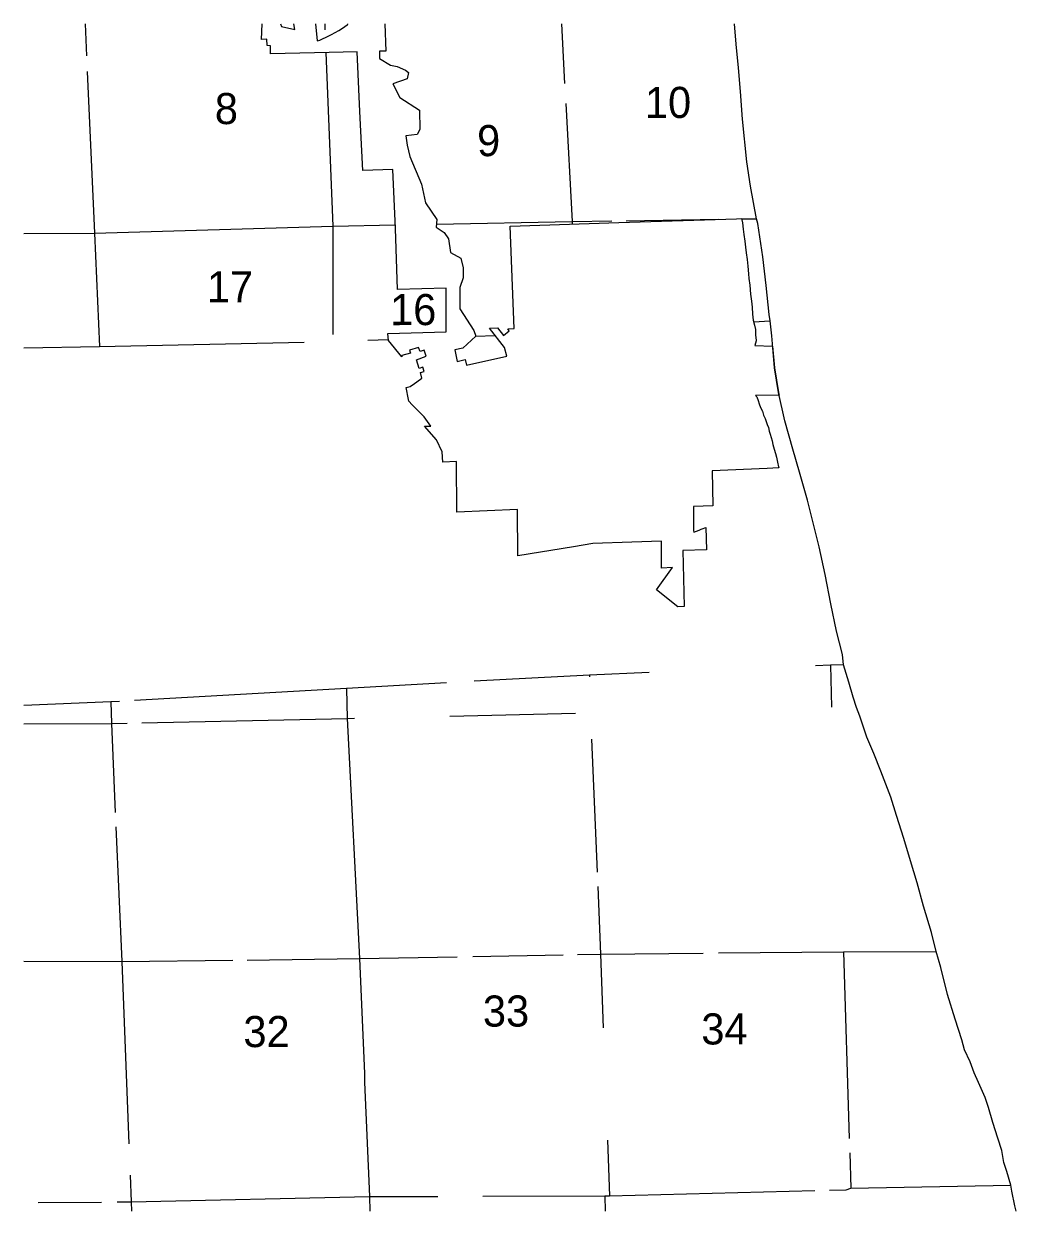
# Model space of a CAD drawing. Extents: x -2251611 to -2054719, y -2227156 to -2099355.
# Drawn here: x -2096698 to -2074784, y -2144490 to -2118284 of the extents above; entities that cross this region are included whole.
import ezdxf

# ---------------------------------------------------------------- set-up
doc = ezdxf.new("R2010")
doc.units = 0
for name, color, linetype in [('tdCoCorpBndry', 7, 'Continuous'), ('tdCoSectLinePart', 7, 'Continuous'), ('tdCoSectNmbr', 7, 'Continuous')]:
    doc.layers.add(name, color=color, linetype=linetype)

msp = doc.modelspace()

# ---------------------------------------------------------------- linework, layer by layer
at = {"layer": 'tdCoCorpBndry'}
for points in [[(-2088724, -2118284), (-2088705, -2118887), (-2088844, -2118891), (-2088842, -2119050), (-2088604, -2119197), (-2088450, -2119224), (-2088268, -2119308), (-2088200, -2119360), (-2088232, -2119497), (-2088546, -2119610), (-2088395, -2119912), (-2087962, -2120191), (-2087954, -2120618), (-2088013, -2120731), (-2088259, -2120757), (-2088230, -2120966), (-2088174, -2121214), (-2087918, -2121827), (-2087828, -2122237), (-2087578, -2122601), (-2087589, -2122774), (-2087416, -2122890), (-2087317, -2123029), (-2087273, -2123331), (-2087050, -2123455), (-2086994, -2123670), (-2086998, -2123894), (-2087071, -2124104), (-2087070, -2124578), (-2086761, -2125054), (-2086720, -2125175), (-2087002, -2125445), (-2087183, -2125483), (-2087130, -2125736), (-2086952, -2125696), (-2086923, -2125816), (-2086030, -2125619), (-2086080, -2125429), (-2086412, -2125000), (-2086240, -2124998), (-2086104, -2125164), (-2085979, -2125060), (-2086009, -2125016), (-2085873, -2125011), (-2085959, -2122752), (-2083559, -2122673), (-2080958, -2122587), (-2080853, -2122584), (-2080831, -2122679), (-2080815, -2122818), (-2080800, -2122938), (-2080778, -2123083), (-2080762, -2123218), (-2080745, -2123336), (-2080727, -2123489), (-2080714, -2123635), (-2080697, -2123802), (-2080685, -2123908), (-2080665, -2124051), (-2080650, -2124254), (-2080632, -2124406), (-2080618, -2124541), (-2080610, -2124693), (-2080592, -2124828), (-2080561, -2124939), (-2080545, -2125034), (-2080538, -2125154), (-2080528, -2125264), (-2080529, -2125285), (-2080556, -2125388), (-2080163, -2125396), (-2080120, -2125877), (-2080034, -2126421), (-2080021, -2126480), (-2080027, -2126480), (-2080539, -2126485), (-2080511, -2126516), (-2080485, -2126601), (-2080460, -2126672), (-2080431, -2126753), (-2080387, -2126837), (-2080362, -2126920), (-2080331, -2126999), (-2080308, -2127062), (-2080281, -2127129), (-2080258, -2127196), (-2080237, -2127273), (-2080218, -2127344), (-2080193, -2127417), (-2080174, -2127491), (-2080158, -2127572), (-2080130, -2127671), (-2080102, -2127768), (-2080081, -2127851), (-2080058, -2127962), (-2080032, -2128059), (-2080025, -2128085), (-2080156, -2128090), (-2080287, -2128096), (-2081495, -2128147), (-2081484, -2128923), (-2081911, -2128941), (-2081907, -2129477), (-2081906, -2129503), (-2081782, -2129457), (-2081739, -2129441), (-2081716, -2129433), (-2081638, -2129404), (-2081621, -2129891), (-2082143, -2129909), (-2082119, -2131143), (-2082257, -2131151), (-2082724, -2130776), (-2082374, -2130282), (-2082620, -2130298), (-2082619, -2130082), (-2082620, -2129704), (-2083271, -2129727), (-2084131, -2129757), (-2084557, -2129827), (-2085788, -2130029), (-2085794, -2129001), (-2087135, -2129063), (-2087141, -2127942), (-2087445, -2127957), (-2087459, -2127728), (-2087582, -2127463), (-2087852, -2127162), (-2087708, -2127162), (-2087858, -2126961), (-2088120, -2126691), (-2088196, -2126612), (-2088203, -2126578), (-2088257, -2126309), (-2088163, -2126286), (-2088112, -2126249), (-2088102, -2126243), (-2087910, -2126106), (-2087939, -2125982), (-2087859, -2125960), (-2087886, -2125862), (-2087966, -2125889), (-2088028, -2125698), (-2087813, -2125617), (-2087855, -2125488), (-2087949, -2125519), (-2087980, -2125428), (-2088180, -2125491), (-2088160, -2125551), (-2088353, -2125605), (-2088348, -2125636), (-2088642, -2125271), (-2088659, -2125118), (-2087371, -2125081), (-2087373, -2124121), (-2088446, -2124147), (-2088489, -2122804), (-2088551, -2121503), (-2089212, -2121520), (-2089274, -2120219), (-2089337, -2118904), (-2089952, -2118919), (-2091247, -2118946), (-2091251, -2118770), (-2091324, -2118762), (-2091333, -2118625), (-2091448, -2118628), (-2091432, -2118284)], [(-2091026, -2118284), (-2091007, -2118341), (-2090715, -2118411), (-2090732, -2118284)], [(-2090256, -2118284), (-2090223, -2118664), (-2090164, -2118643), (-2089964, -2118552), (-2089905, -2118523), (-2089739, -2118432), (-2089657, -2118383), (-2089559, -2118308), (-2089545, -2118298), (-2089546, -2118284)]]:
    msp.add_lwpolyline(points, dxfattribs=at)
at = {"layer": 'tdCoSectLinePart'}
for p, q in [((-2095345, -2118284), (-2095314, -2118990)), ((-2090053, -2118284), (-2090048, -2118416)), ((-2084825, -2118284), (-2084755, -2119606)), ((-2096698, -2122916), (-2095139, -2122909)), ((-2096698, -2125433), (-2095024, -2125403)), ((-2094773, -2133251), (-2096698, -2133327)), ((-2096698, -2133734), (-2094762, -2133728)), ((-2096698, -2138970), (-2094533, -2138982)), ((-2089061, -2144167), (-2089056, -2144490)), ((-2083866, -2144148), (-2083861, -2144490)), ((-2094326, -2144284), (-2094322, -2144490))]:
    msp.add_line(p, q, dxfattribs=at)
for points in [[(-2080519, -2122587), (-2080651, -2121866), (-2080732, -2121334), (-2080828, -2120390), (-2080869, -2119780), (-2080916, -2119260), (-2080969, -2118734), (-2081002, -2118284)], [(-2090028, -2118920), (-2089875, -2122752)], [(-2095298, -2119336), (-2095139, -2122909)], [(-2084731, -2120046), (-2084593, -2122649)], [(-2087586, -2122708), (-2084593, -2122649)], [(-2084593, -2122649), (-2083717, -2122636)], [(-2084593, -2122649), (-2084592, -2122707)], [(-2083398, -2122631), (-2081355, -2122600)], [(-2080853, -2122592), (-2080519, -2122587)], [(-2080221, -2124837), (-2080236, -2124702), (-2080307, -2124061), (-2080378, -2123430), (-2080489, -2122692), (-2080519, -2122587)], [(-2095139, -2122909), (-2089875, -2122752)], [(-2095139, -2122909), (-2095024, -2125403)], [(-2089875, -2122752), (-2088494, -2122725)], [(-2089875, -2122752), (-2089871, -2125140)], [(-2080585, -2124859), (-2080221, -2124837)], [(-2078596, -2132435), (-2078619, -2132203), (-2078751, -2131689), (-2078875, -2131088), (-2079003, -2130438), (-2079138, -2129825), (-2079266, -2129300), (-2079393, -2128796), (-2079570, -2128183), (-2079717, -2127671), (-2079896, -2127049), (-2080036, -2126421), (-2080122, -2125877), (-2080184, -2125168), (-2080221, -2124837)], [(-2095024, -2125403), (-2090506, -2125311)], [(-2089100, -2125269), (-2088646, -2125251)], [(-2086725, -2125178), (-2086289, -2125162)], [(-2086113, -2125155), (-2086094, -2125154)], [(-2084210, -2132656), (-2086751, -2132795)], [(-2082892, -2132602), (-2084210, -2132656)], [(-2084210, -2132656), (-2084209, -2132698)], [(-2078883, -2132440), (-2079215, -2132453)], [(-2078596, -2132435), (-2078883, -2132440)], [(-2078883, -2132440), (-2078865, -2133364)], [(-2078312, -2133370), (-2078384, -2133144), (-2078484, -2132817), (-2078596, -2132435)], [(-2087365, -2132829), (-2089572, -2132951)], [(-2089572, -2132951), (-2094256, -2133221)], [(-2089572, -2132951), (-2089554, -2133614)], [(-2094583, -2133240), (-2094773, -2133251)], [(-2094773, -2133251), (-2094762, -2133728)], [(-2076556, -2138755), (-2076655, -2138342), (-2076830, -2137761), (-2076972, -2137244), (-2077118, -2136756), (-2077264, -2136264), (-2077427, -2135756), (-2077553, -2135354), (-2077772, -2134780), (-2077930, -2134386), (-2078085, -2134028), (-2078237, -2133565), (-2078312, -2133370)], [(-2094093, -2133713), (-2089554, -2133614)], [(-2089554, -2133614), (-2089397, -2133611)], [(-2089554, -2133614), (-2089287, -2138916)], [(-2087289, -2133563), (-2084516, -2133501)], [(-2094762, -2133728), (-2094415, -2133720)], [(-2094762, -2133728), (-2094677, -2135687)], [(-2084163, -2134073), (-2084038, -2137010)], [(-2094663, -2136010), (-2094533, -2138982)], [(-2084024, -2137326), (-2083961, -2138815)], [(-2094533, -2138982), (-2092079, -2138951)], [(-2091763, -2138947), (-2089287, -2138916)], [(-2089287, -2138916), (-2087126, -2138875)], [(-2089287, -2138916), (-2089171, -2141451), (-2089177, -2141639), (-2089061, -2144167)], [(-2086783, -2138869), (-2084788, -2138831)], [(-2084471, -2138825), (-2083961, -2138815)], [(-2083961, -2138815), (-2081695, -2138793)], [(-2083961, -2138815), (-2083902, -2140441)], [(-2081359, -2138790), (-2078601, -2138763)], [(-2078601, -2138763), (-2076556, -2138755)], [(-2078601, -2138763), (-2078472, -2142883)], [(-2074906, -2143912), (-2074995, -2143613), (-2075055, -2143411), (-2075105, -2143146), (-2075188, -2142879), (-2075298, -2142528), (-2075400, -2142201), (-2075469, -2141978), (-2075618, -2141649), (-2075712, -2141434), (-2075804, -2141195), (-2075930, -2140927), (-2075986, -2140709), (-2076134, -2140252), (-2076304, -2139707), (-2076449, -2139108), (-2076556, -2138755)], [(-2094533, -2138982), (-2094376, -2143004)], [(-2083811, -2142923), (-2083767, -2144148)], [(-2078462, -2143201), (-2078437, -2143982)], [(-2094349, -2143691), (-2094326, -2144284)], [(-2078437, -2143982), (-2074906, -2143912)], [(-2074784, -2144490), (-2074817, -2144372), (-2074881, -2144044), (-2074906, -2143912)], [(-2094326, -2144284), (-2089061, -2144167)], [(-2089061, -2144167), (-2087559, -2144161)], [(-2086563, -2144158), (-2083866, -2144148)], [(-2083866, -2144148), (-2083767, -2144148)], [(-2083767, -2144148), (-2079231, -2144035)], [(-2078909, -2144027), (-2078541, -2144018)], [(-2078541, -2144018), (-2078437, -2143982)], [(-2096382, -2144296), (-2094982, -2144288)], [(-2094634, -2144285), (-2094326, -2144284)]]:
    msp.add_lwpolyline(points, dxfattribs=at)

# ---------------------------------------------------------------- texts
at = {"layer": 'tdCoSectNmbr'}
for s, height, rotation, p in [('8', 686, 0.0882, (-2092479, -2120499)), ('10', 686.4, 0.0896, (-2082982, -2120364)), ('9', 686, 0.089, (-2086688, -2121206)), ('17', 686.4, 0.0881, (-2092653, -2124432)), ('16', 686.4, 0.0889, (-2088609, -2124936)), ('33', 686.4, 0.089, (-2086560, -2140416)), ('32', 686.4, 0.0881, (-2091848, -2140868)), ('34', 686.4, 0.0898, (-2081737, -2140810))]:
    msp.add_text(s, height=height, rotation=rotation, dxfattribs=at).set_placement(p)

doc.saveas('drawing.dxf')
